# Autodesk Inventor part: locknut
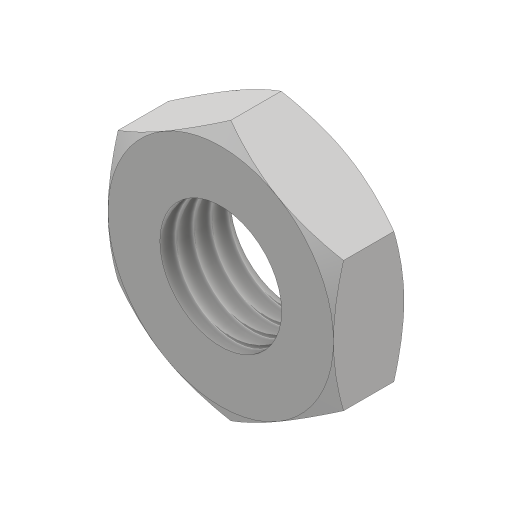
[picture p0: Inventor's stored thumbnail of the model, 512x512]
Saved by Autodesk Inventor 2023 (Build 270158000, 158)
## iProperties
Created: 2016-05
Part Number: locknut
Material: Generic
Document SubType Name: Modeling
Designer: CADCIM
Density: 1 g/cm^3
Appearance: Default
Author: CADCIM
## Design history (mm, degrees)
sketch "Sketch1"
  geometry: L1 (9.6, -5.543)-(0, -11.085); L2 (0, -11.085)-(-9.6, -5.543); L3 (-9.6, -5.543)-(-9.6, 5.543); L4 (-9.6, 5.543)-(0, 11.085); L5 (0, 11.085)-(9.6, 5.543); L6 (9.6, 5.543)-(9.6, -5.543); 2 further points
  constraints: 12 end point, 1 coincident, 1 vertical alignment, 13 other
  dimensions: "d0" = 19.2 distance between parallel lines of L3 L6
extrude "Extrusion1" new body sketch "Sketch1" distance "d1" = 6; taper "d2" = 0 deg
sketch "Sketch2"
  geometry: L1 (0, 11.085)-(-9.6, 5.543) reference; C1 r 9.6 at (0, 0); 1 further point
  constraints: 1 centre point, 1 coincident, 1 tangent
extrude "Extrusion2" sketch "Sketch2" distance "d3" = 10.8; taper "d4" = 60 deg
workplane "Work Plane1"
sketch "Sketch3"
  geometry: L1 (0, -11.085)-(9.6, -5.543) reference; C1 r 9.6 at (0, 0); 1 further point
  constraints: 1 centre point, 1 coincident, 1 tangent
extrude "Extrusion3" sketch "Sketch3" distance "d5" = 10.8; taper "d6" = 60 deg
sketch "Sketch4"
  geometry: 1 further point
hole "Hole1" diameter "d9" = 10.376; stored, may be unused: countersink angle "d13" = 90 deg, drill point angle "d15" = 118 deg; dims "d7" = 10, "d8" = 10, "d10" = 24, "d11" = 4, "d12" = 2, "d14" = 31.3
body "Solid1"
